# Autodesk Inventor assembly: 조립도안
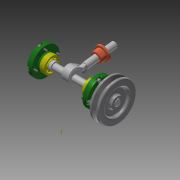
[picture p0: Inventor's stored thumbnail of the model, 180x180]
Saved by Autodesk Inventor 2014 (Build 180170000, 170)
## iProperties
Created: 2017-07
Part Number: 조립도안
Document SubType Name: Assembly
Designer: user
Author: user
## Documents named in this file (16)
- C:\Users\user\Desktop\470708V1007\조립도안.iam
- C:\Users\user\Desktop\470708V1007\V벨트풀리.ipt
- C:\Users\user\Desktop\470708V1007\고정핀 1.2 x  8.ipt
- C:\Users\user\Desktop\470708V1007\뒤커버.ipt
- C:\Users\user\Desktop\470708V1007\링크.ipt
- C:\Users\user\Desktop\470708V1007\멈춤나사 M3x8.ipt
- C:\Users\user\Desktop\470708V1007\베어링 12 x 32 x 10.ipt
- C:\Users\user\Desktop\470708V1007\본체.ipt
- C:\Users\user\Desktop\470708V1007\볼트 M4 x 12.ipt
- C:\Users\user\Desktop\470708V1007\부시.ipt
- C:\Users\user\Desktop\470708V1007\슬라이드.ipt
- C:\Users\user\Desktop\470708V1007\앞커버.ipt
- C:\Users\user\Desktop\470708V1007\오일실 12 25 7.ipt
- C:\Users\user\Desktop\470708V1007\키 4 x 4 x 10.ipt
- C:\Users\user\Desktop\470708V1007\편심축.ipt
- C:\Users\user\Desktop\470708V1007\핀 5 x 18.ipt
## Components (3 placed, 3 different names)
1. V벨트풀리:1 — Mate:10, Mate:12, Mate:13
2. 고정핀 1.2 x  8:1 — Mate:41, Mate:46
3. 핀 5 x 18:1 — Mate:41, Mate:43, Mate:44, Mate:46
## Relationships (7: Mate 7)
- Mate:10: V벨트풀리:1
- Mate:12: V벨트풀리:1
- Mate:13: V벨트풀리:1
- Mate:41: 고정핀 1.2 x  8:1 ↔ 핀 5 x 18:1
- Mate:43: 핀 5 x 18:1
- Mate:44: 핀 5 x 18:1
- Mate:46: 고정핀 1.2 x  8:1 ↔ 핀 5 x 18:1
